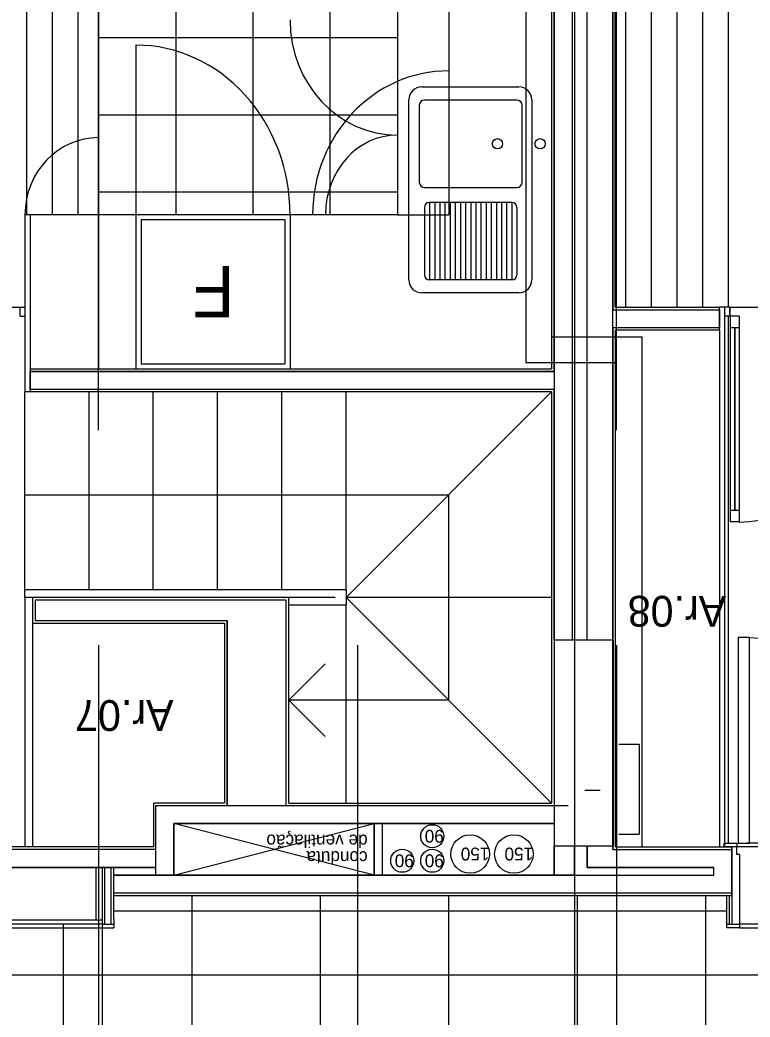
# Model space of a CAD drawing. Extents: x 1248 to 1356, y -443 to -224.
# Drawn here: x 1301.25 to 1304.091, y -237.588 to -233.707 of the extents above; entities that cross this region are included whole.
import ezdxf

# ---------------------------------------------------------------- set-up
doc = ezdxf.new("R2010")
doc.units = 0
for name, color, linetype in [('corte', 7, 'Continuous'), ('estereoctomias', 7, 'Continuous'), ('Level 1', 7, 'Continuous'), ('Level 10', 7, 'Continuous'), ('Level 11', 7, 'Continuous'), ('Level 13', 7, 'Continuous'), ('Level 2', 7, 'Continuous'), ('Level 21', 7, 'Continuous'), ('Level 3', 7, 'Continuous'), ('Level 36', 7, 'Continuous'), ('Level 4', 7, 'Continuous'), ('Level 40', 7, 'Continuous'), ('Level 41', 7, 'Continuous'), ('mob-fixo', 7, 'Continuous'), ('projeccao', 7, 'Continuous'), ('revestimentos', 7, 'Continuous'), ('vermelhos-cont', 7, 'Continuous'), ('vermelhos-tracej', 7, 'Continuous')]:
    doc.layers.add(name, color=color, linetype=linetype)

msp = doc.modelspace()

# ---------------------------------------------------------------- linework, layer by layer
at = {"layer": 'corte'}
for p, q in [((1303.5575, -235.1452), (1303.5575, -231.934)), ((1303.329, -232.2659), (1303.329, -235.1452)), ((1303.399, -232.7639), (1303.399, -236.1213)), ((1303.457, -236.1213), (1303.457, -232.7639)), ((1303.329, -235.1452), (1303.329, -237.0363)), ((1303.5575, -236.9359), (1303.5575, -235.1452)), ((1301.7783, -236.9359), (1301.7783, -236.7652)), ((1301.8483, -237.0363), (1301.8483, -236.8352)), ((1302.629, -236.8352), (1302.629, -237.0363)), ((1302.659, -236.8352), (1302.659, -237.0363)), ((1303.4068, -236.9213), (1303.4068, -237.0363)), ((1303.4568, -236.9213), (1303.4568, -237.0059)), ((1304.0204, -237.1163), (1304.0204, -236.9259)), ((1301.6154, -237.1063), (1301.6154, -237.0363)), ((1301.7783, -237.0363), (1301.7783, -237.0059)), ((1303.4068, -237.0363), (1303.9504, -237.0363)), ((1303.9504, -237.0363), (1303.9504, -237.0059)), ((1303.3419, -237.1063), (1301.6154, -237.1063)), ((1304.0204, -237.1063), (1303.3275, -237.1063))]:
    msp.add_line(p, q, dxfattribs=at)
for points in [[(1303.329, -236.9213), (1303.559, -236.9213), (1303.559, -236.1213), (1303.329, -236.1213)], [(1303.3294, -236.9213), (1303.5594, -236.9213), (1303.5594, -236.1213), (1303.3294, -236.1213)]]:
    msp.add_lwpolyline(points, close=True, dxfattribs=at)
at = {"layer": 'estereoctomias'}
for p, q in [((1301.2762, -234.4652), (1301.2762, -232.2759)), ((1301.3762, -234.4652), (1301.3762, -232.2759)), ((1301.4762, -234.4652), (1301.4762, -232.2759)), ((1304.8504, -237.2259), (1304.0504, -237.2259))]:
    msp.add_line(p, q, dxfattribs=at)
for points in [[(1303.399, -232.7639), (1303.399, -236.1213), (1303.329, -236.1213), (1303.329, -235.1452), (1301.2894, -235.1452), (1301.2894, -235.0752), (1303.329, -235.0752), (1303.329, -232.7639)], [(1303.457, -232.7639), (1303.5575, -232.7639), (1303.5575, -234.8352), (1303.9719, -234.8352), (1303.9719, -234.9052), (1303.5568, -234.9051), (1303.5575, -236.1213), (1303.457, -236.1213)], [(1302.2864, -236.7652), (1302.2864, -235.9652), (1301.309, -235.9652), (1301.309, -236.0452), (1302.0564, -236.0452), (1302.0564, -236.7652)], [(1303.329, -236.7652), (1303.329, -236.8352), (1301.8483, -236.8352), (1301.8483, -237.0363), (1301.7783, -237.0363), (1301.7783, -236.7652)], [(1302.659, -236.8352), (1302.659, -237.0363), (1302.629, -237.0363), (1302.629, -236.8352)], [(1304.0204, -236.9359), (1304.0204, -237.1063), (1301.6154, -237.1063), (1301.6154, -237.0363), (1303.9504, -237.0363), (1303.9504, -237.0059), (1303.4568, -237.0059), (1303.4568, -236.9213), (1303.5575, -236.9213), (1303.5575, -236.9359), (1304.0204, -236.9359)], [(1303.4068, -236.9213), (1303.4068, -237.0363), (1303.329, -237.0363), (1303.329, -236.9213)], [(1301.7783, -236.9359), (1300.8504, -236.9359), (1300.8504, -237.2109), (1300.9204, -237.2109), (1300.9204, -237.0059), (1301.7783, -237.0059)]]:
    msp.add_lwpolyline(points, close=True, dxfattribs=at)
at = {"layer": 'Level 1'}
for p, q in [((1303.9719, -234.9152), (1303.9719, -234.8252)), ((1303.5575, -234.8352), (1303.9719, -234.8352)), ((1303.9719, -234.9052), (1303.5568, -234.9052)), ((1301.2894, -235.0652), (1301.2894, -235.1552)), ((1303.329, -235.0752), (1301.2894, -235.0752)), ((1303.329, -235.1452), (1301.2894, -235.1452)), ((1302.2864, -235.9652), (1301.309, -235.9652)), ((1301.309, -235.9652), (1301.309, -236.0452)), ((1302.2864, -236.7652), (1302.2864, -235.9652)), ((1301.309, -236.0452), (1302.0564, -236.0452)), ((1302.0564, -236.7652), (1302.0564, -236.0452)), ((1303.4485, -236.7052), (1303.5085, -236.7052)), ((1301.7783, -236.7652), (1303.3829, -236.7652)), ((1301.8483, -236.8352), (1303.329, -236.8352)), ((1301.7783, -236.9359), (1300.8504, -236.9359)), ((1303.5575, -236.9359), (1304.0204, -236.9359)), ((1301.7783, -237.0059), (1300.9204, -237.0059)), ((1301.7783, -237.0363), (1301.6154, -237.0363)), ((1303.329, -237.0363), (1301.8483, -237.0363)), ((1303.4568, -237.0059), (1303.9504, -237.0059))]:
    msp.add_line(p, q, dxfattribs=at)
at = {"layer": 'Level 10'}
for p, q in [((1301.5562, -232.2759), (1301.5562, -234.4652)), ((1301.8562, -232.2759), (1301.8562, -234.4652)), ((1302.1562, -232.2759), (1302.1562, -234.4652)), ((1302.4562, -232.2759), (1302.4562, -234.4652)), ((1303.6062, -232.2759), (1303.6062, -234.8252)), ((1303.7062, -232.2759), (1303.7062, -234.8252)), ((1303.8062, -232.2759), (1303.8062, -234.8252)), ((1303.9062, -232.2759), (1303.9062, -234.8252)), ((1304.0062, -232.2759), (1304.0062, -234.8252)), ((1304.0062, -234.8602), (1304.0062, -236.9109)), ((1304.8604, -236.9259), (1304.0404, -236.9259)), ((1301.9183, -237.1163), (1301.9183, -238.724)), ((1302.4183, -237.1163), (1302.4183, -238.724)), ((1302.9183, -237.1163), (1302.9183, -238.724)), ((1303.4183, -237.1163), (1303.4183, -238.724)), ((1303.9183, -237.1163), (1303.9183, -238.724)), ((1301.6154, -237.174), (1304.0004, -237.174)), ((1301.4183, -237.2259), (1301.4183, -238.624)), ((1296.6633, -237.424), (1318.1944, -237.424))]:
    msp.add_line(p, q, dxfattribs=at)
at = {"layer": 'Level 11'}
for p, q in [((1302.2812, -234.4852), (1301.7212, -234.4852)), ((1301.7212, -234.4852), (1301.7212, -235.0452)), ((1302.2812, -234.4852), (1302.2812, -235.0452)), ((1301.7212, -235.0452), (1302.2812, -235.0452))]:
    msp.add_line(p, q, dxfattribs=at)
at = {"layer": 'Level 13'}
for p, q in [((1301.2894, -234.4652), (1301.2694, -234.4652)), ((1301.2694, -234.4652), (1301.2694, -235.1552)), ((1301.2894, -234.4652), (1301.2894, -235.0652)), ((1301.2509, -234.8602), (1301.2509, -234.8252)), ((1301.2509, -234.8252), (1301.2709, -234.8252)), ((1303.9919, -234.8252), (1303.9719, -234.8252)), ((1303.9919, -234.8252), (1303.9919, -236.9259)), ((1304.0119, -234.8252), (1303.9919, -234.8252)), ((1304.0119, -234.8252), (1304.0119, -234.8602)), ((1301.2509, -234.8602), (1301.2709, -234.8602)), ((1304.0119, -234.8602), (1303.9919, -234.8602)), ((1304.0139, -234.8602), (1304.0139, -235.661)), ((1304.0489, -234.8602), (1304.0139, -234.8602)), ((1304.0489, -234.8602), (1304.0489, -235.661)), ((1304.0489, -234.9052), (1304.0139, -234.9052)), ((1303.9719, -234.9152), (1303.9719, -236.9259)), ((1301.2894, -235.1552), (1301.2694, -235.1552)), ((1304.0489, -235.616), (1304.0139, -235.616)), ((1304.0489, -235.661), (1304.0139, -235.661)), ((1301.269, -235.9552), (1301.269, -236.9259)), ((1301.299, -235.9552), (1301.269, -235.9552)), ((1301.299, -235.9552), (1301.299, -236.9259)), ((1304.0454, -236.1109), (1304.0454, -236.9109)), ((1304.0894, -236.1109), (1304.0454, -236.1109)), ((1304.0894, -236.9109), (1304.0894, -236.1109)), ((1304.0204, -236.9259), (1304.0204, -237.2259)), ((1304.0404, -236.9549), (1304.0404, -236.9259)), ((1304.0454, -236.9109), (1304.0894, -236.9109)), ((1304.0504, -236.9549), (1304.0404, -236.9549)), ((1304.0504, -236.9549), (1304.0504, -237.2259)), ((1301.5704, -237.0059), (1301.5704, -237.2259)), ((1301.5804, -237.2259), (1301.5804, -237.0059)), ((1301.6054, -237.2259), (1301.6054, -237.0059)), ((1301.6154, -237.2059), (1301.6154, -237.0059)), ((1304.0004, -237.2409), (1304.0004, -237.1163)), ((1304.0104, -237.1163), (1304.0104, -237.2259)), ((1301.5704, -237.2109), (1300.8204, -237.2109)), ((1301.5704, -237.2259), (1300.8604, -237.2259)), ((1301.5704, -237.2259), (1300.8604, -237.2259)), ((1301.5704, -237.2259), (1300.8704, -237.2259)), ((1301.5704, -237.2109), (1301.5704, -237.2259)), ((1301.5704, -237.2259), (1301.5704, -237.2409)), ((1301.5704, -237.2259), (1301.6154, -237.2259)), ((1301.6154, -237.2059), (1301.6154, -237.2259)), ((1301.6154, -237.2259), (1301.6154, -237.2409)), ((1304.0004, -237.2259), (1304.0504, -237.2259)), ((1304.0504, -237.2259), (1304.0504, -237.2409)), ((1301.5704, -237.2409), (1301.6154, -237.2409)), ((1304.0504, -237.2409), (1304.0004, -237.2409))]:
    msp.add_line(p, q, dxfattribs=at)
msp.add_lwpolyline([(1304.0404, -236.9259), (1303.9904, -236.9259), (1303.9904, -236.9109), (1304.0404, -236.9109)], close=True, dxfattribs=at)
at = {"layer": 'Level 2'}
for p, q in [((1302.719, -232.2759), (1302.719, -234.4652)), ((1302.8041, -234.0391), (1302.8041, -234.3391)), ((1303.1841, -234.0191), (1302.8241, -234.0191)), ((1303.2041, -234.3391), (1303.2041, -234.0391)), ((1302.8241, -234.3591), (1303.1841, -234.3591)), ((1302.8241, -234.4375), (1302.8241, -234.6991)), ((1303.1641, -234.4175), (1302.8441, -234.4175)), ((1302.8441, -234.4175), (1302.8441, -234.7191)), ((1302.8641, -234.4175), (1302.8641, -234.7191)), ((1302.8841, -234.4175), (1302.8841, -234.7191)), ((1302.9041, -234.4175), (1302.9041, -234.7191)), ((1302.9241, -234.4175), (1302.9241, -234.7191)), ((1302.9441, -234.4175), (1302.9441, -234.7191)), ((1302.9641, -234.4175), (1302.9641, -234.7191)), ((1302.9841, -234.4175), (1302.9841, -234.7191)), ((1303.0041, -234.4175), (1303.0041, -234.7191)), ((1303.0241, -234.4175), (1303.0241, -234.7191)), ((1303.0441, -234.4175), (1303.0441, -234.7191)), ((1303.0641, -234.4175), (1303.0641, -234.7191)), ((1303.0841, -234.4175), (1303.0841, -234.7191)), ((1303.1041, -234.4175), (1303.1041, -234.7191)), ((1303.1241, -234.4175), (1303.1241, -234.7191)), ((1303.1441, -234.4175), (1303.1441, -234.7191)), ((1303.1641, -234.4175), (1303.1641, -234.7191)), ((1303.1841, -234.4375), (1303.1841, -234.6991)), ((1302.719, -234.4652), (1301.2894, -234.4652)), ((1302.6762, -234.4652), (1301.5101, -234.4652)), ((1302.6762, -234.4652), (1301.5101, -234.4652)), ((1301.7012, -234.4652), (1301.7012, -235.0652)), ((1301.7012, -234.4652), (1301.7012, -235.0652)), ((1302.3012, -234.4652), (1302.3012, -235.0652)), ((1302.3012, -234.4652), (1302.3012, -235.0652)), ((1303.1641, -234.7191), (1302.8441, -234.7191)), ((1301.269, -235.9552), (1301.269, -235.1552)), ((1301.2694, -235.1552), (1301.2694, -235.1552)), ((1301.519, -235.9252), (1301.519, -235.1552)), ((1301.769, -235.9252), (1301.769, -235.1552)), ((1302.019, -235.9252), (1302.019, -235.1552)), ((1302.269, -235.9252), (1302.269, -235.1552)), ((1302.519, -235.9252), (1302.519, -235.1552)), ((1302.519, -235.9552), (1303.319, -235.1552)), ((1301.269, -235.5552), (1302.919, -235.5552)), ((1302.919, -236.3552), (1302.919, -235.5552)), ((1302.519, -235.9252), (1301.269, -235.9252)), ((1302.4764, -235.9552), (1301.2717, -235.9552)), ((1302.4764, -235.9552), (1301.2986, -235.9552)), ((1302.519, -235.9252), (1302.519, -235.9852)), ((1303.319, -235.9552), (1302.519, -235.9552)), ((1302.519, -235.9552), (1303.319, -236.7552)), ((1302.519, -235.9852), (1302.2964, -235.9852)), ((1302.519, -236.7552), (1302.519, -235.9852)), ((1302.4378, -236.2137), (1302.2964, -236.3552)), ((1302.919, -236.3552), (1302.2964, -236.3552)), ((1302.4378, -236.4966), (1302.2964, -236.3552))]:
    msp.add_line(p, q, dxfattribs=at)
for points in [[(1302.8136, -233.9679), (1303.192, -233.9679)], [(1302.7636, -234.7193), (1302.7636, -234.0179)], [(1303.242, -234.0179), (1303.242, -234.7193)], [(1303.192, -234.7693), (1302.8136, -234.7693)]]:
    msp.add_lwpolyline(points, dxfattribs=at)
for centre in [(1303.1081, -234.1891), (1303.2741, -234.1891)]:
    msp.add_circle(centre, 0.0199, dxfattribs=at)
for centre, radius, start, end in [((1302.8136, -234.0179), 0.05, 90, 180), ((1303.192, -234.0179), 0.05, 360, 90), ((1302.8241, -234.0391), 0.02, 90, 180), ((1303.1841, -234.0391), 0.02, 360, 90), ((1302.8241, -234.3391), 0.02, 180, 270), ((1303.1841, -234.3391), 0.02, 270, 0), ((1302.8441, -234.4375), 0.02, 90, 180), ((1303.1641, -234.4375), 0.02, 0, 90), ((1302.8441, -234.6991), 0.02, 180, 270), ((1303.1641, -234.6991), 0.02, 270, 0), ((1302.8136, -234.7193), 0.05, 180, 270), ((1303.192, -234.7193), 0.05, 270, 360)]:
    msp.add_arc(centre, radius, start, end, dxfattribs=at)
at = {"layer": 'Level 21'}
for p, q in [((1301.5562, -233.7759), (1302.719, -233.7759)), ((1301.5562, -234.0759), (1302.719, -234.0759)), ((1301.5562, -234.3759), (1302.719, -234.3759))]:
    msp.add_line(p, q, dxfattribs=at)
at = {"layer": 'Level 3'}
for p in [(1302.919, -232.2759), (1302.719, -234.4652)]:
    msp.add_line(p, (1302.919, -234.4652), dxfattribs=at)
at = {"layer": 'Level 36'}
for p, q in [((1304.0304, -234.9052), (1304.0304, -235.616)), ((1304.0324, -234.9052), (1304.0324, -235.616))]:
    msp.add_line(p, q, dxfattribs=at)
at = {"layer": 'Level 4'}
for p, q in [((1301.7012, -233.8052), (1301.7012, -234.4652)), ((1301.5562, -234.4652), (1301.5562, -234.2652)), ((1301.5562, -234.4652), (1301.5562, -235.0652)), ((1299.9804, -234.8252), (1301.2694, -234.8252)), ((1304.0104, -234.8252), (1305.2994, -234.8252)), ((1304.0139, -234.8602), (1304.0139, -234.8252)), ((1303.5804, -236.5259), (1303.6604, -236.5259)), ((1303.6604, -236.5259), (1303.6604, -236.8759)), ((1303.5804, -236.8759), (1303.6604, -236.8759)), ((1304.8504, -236.9109), (1304.0794, -236.9109)), ((1301.5454, -237.0059), (1301.5454, -237.2109)), ((1301.5704, -237.2259), (1301.5704, -237.9259)), ((1300.0204, -237.2409), (1301.5704, -237.2409)), ((1304.0504, -237.2409), (1305.6004, -237.2409))]:
    msp.add_line(p, q, dxfattribs=at)
msp.add_arc((1301.5704, -237.2259), 0.7, 181.2279, 270, dxfattribs=at)
for centre, major_axis, ratio, start_param, end_param in [((1302.719, -233.7072), (0, -0.448), 0.933036, 4.712389, 6.283185), ((1301.7012, -234.4652), (0, -0.66), 0.909091, 1.570796, 3.141593), ((1302.919, -234.4652), (0, -0.56), 0.946429, 3.141593, 4.712389), ((1302.719, -234.4652), (0, -0.31), 0.903226, 3.141593, 4.712389), ((1304.0544, -236.9109), (-0.806, 0), 0.992512, 3.141593, 4.668897)]:
    msp.add_ellipse(centre, major_axis=major_axis, ratio=ratio, start_param=start_param, end_param=end_param, dxfattribs=at)
at = {"layer": 'Level 41'}
for p, q in [((1302.629, -237.0363), (1301.8483, -236.8352)), ((1301.8483, -237.0363), (1302.629, -236.8352))]:
    msp.add_line(p, q, dxfattribs=at)
for centre, radius in [((1302.8547, -236.8843), 0.045), ((1303.002, -236.9535), 0.075), ((1303.1722, -236.9535), 0.075), ((1302.7379, -236.9797), 0.045), ((1302.8547, -236.9797), 0.045)]:
    msp.add_circle(centre, radius, dxfattribs=at)
at = {"layer": 'mob-fixo'}
for p, q in [((1303.219, -232.609), (1303.219, -235.0402)), ((1303.319, -234.9402), (1303.6719, -234.9402)), ((1303.6719, -236.9259), (1303.6719, -234.9402)), ((1303.219, -235.0402), (1303.5719, -235.0402))]:
    msp.add_line(p, q, dxfattribs=at)
at = {"layer": 'projeccao'}
msp.add_arc((1304.0196, -234.8658), 0.7962, 272.1092, 2.9297, dxfattribs=at)
msp.add_ellipse((1301.5562, -234.4652), major_axis=(0, -0.3), ratio=0.955814, start_param=3.141593, end_param=4.712389, dxfattribs=at)
at = {"layer": 'revestimentos'}
for p, q in [((1303.5668, -234.8252), (1303.5668, -231.924)), ((1303.319, -232.2759), (1303.319, -235.0652)), ((1303.5668, -234.8252), (1303.9719, -234.8252)), ((1303.5675, -236.9259), (1303.5675, -234.9152)), ((1303.9719, -234.9152), (1303.5675, -234.9152)), ((1303.319, -235.1552), (1301.2894, -235.1552)), ((1303.319, -235.1552), (1303.319, -236.7552)), ((1302.2964, -235.9552), (1301.299, -235.9552)), ((1301.299, -235.9552), (1301.299, -236.0552)), ((1302.2964, -236.7552), (1302.2964, -235.9552)), ((1301.299, -236.0552), (1302.0464, -236.0552)), ((1302.0464, -236.0552), (1302.0464, -236.7552)), ((1302.0464, -236.7552), (1301.7712, -236.7552)), ((1301.7712, -236.9259), (1301.7712, -236.7552)), ((1302.2964, -236.7552), (1303.319, -236.7552)), ((1301.7712, -236.9259), (1300.8504, -236.9259)), ((1303.5675, -236.9259), (1304.0204, -236.9259)), ((1304.0219, -237.1163), (1301.6154, -237.1163)), ((1304.0204, -237.1163), (1303.3275, -237.1163))]:
    msp.add_line(p, q, dxfattribs=at)
msp.add_lwpolyline([(1301.2894, -235.0652), (1303.319, -235.0652)], dxfattribs=at)
at = {"layer": 'vermelhos-cont'}
msp.add_line((1303.4094, -250.7923), (1303.4094, -229.6087), dxfattribs=at)
at = {"layer": 'vermelhos-tracej'}
for p, q in [((1301.5562, -235.3039), (1301.5562, -224.3117)), ((1303.5712, -235.3039), (1303.5712, -224.3117)), ((1301.5573, -246.757), (1301.5573, -236.1407)), ((1302.5648, -246.757), (1302.5648, -236.1407)), ((1303.5723, -246.757), (1303.5723, -236.1407))]:
    msp.add_line(p, q, dxfattribs=at)

# ---------------------------------------------------------------- texts
at = {"layer": 'Level 11'}
msp.add_text('F', height=0.2, rotation=180, dxfattribs=at).set_placement((1302.0851, -234.6651))
at = {"layer": 'Level 40'}
for s, p in [('Ar.08', (1303.9986, -235.9486)), ('Ar.07', (1301.8478, -236.3544))]:
    msp.add_text(s, height=0.12, rotation=180, dxfattribs=at).set_placement(p)
at = {"layer": 'Level 41'}
for s, p in [('de ventilação ', (1302.603, -236.878)), ('90', (1302.8997, -236.8593)), ('150', (1303.077, -236.9285)), ('150', (1303.2472, -236.9285)), ('conduta', (1302.603, -236.9424)), ('90', (1302.7829, -236.9547)), ('90', (1302.8997, -236.9547))]:
    msp.add_text(s, height=0.05, rotation=180, dxfattribs=at).set_placement(p)

doc.saveas('drawing.dxf')
